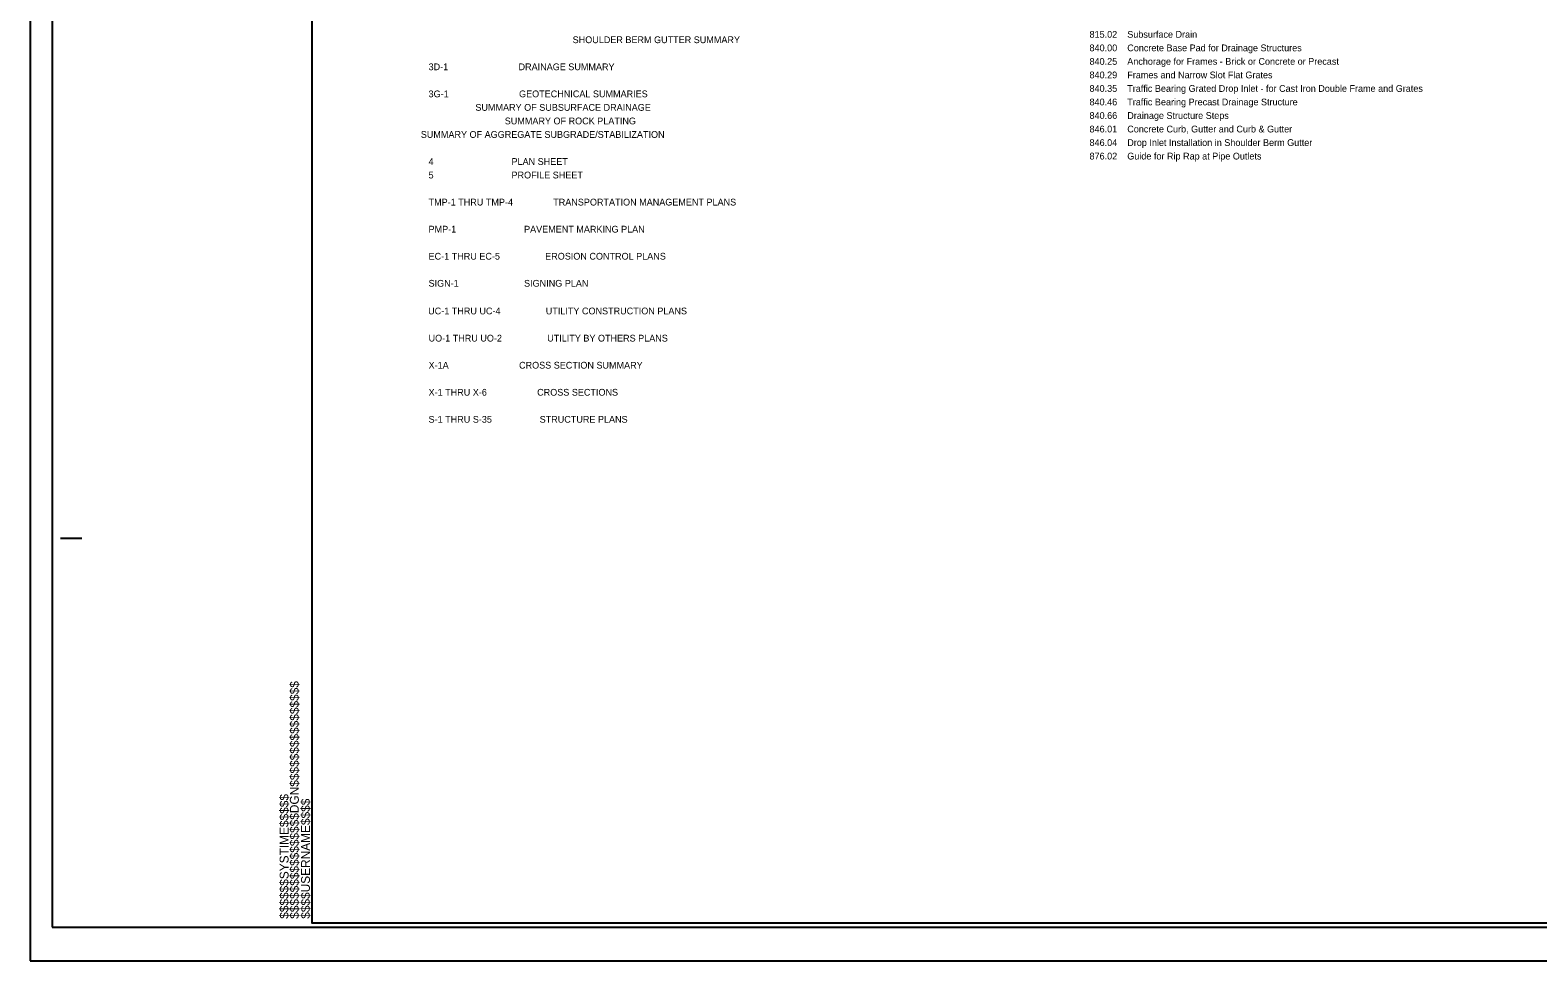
# Model space of a CAD drawing. Extents: x 9834 to 11517, y 9978 to 11072.
# Drawn here: x 9834 to 10725, y 9978 to 10528 of the extents above; entities that cross this region are included whole.
import ezdxf

# ---------------------------------------------------------------- set-up
doc = ezdxf.new("R2010")
doc.units = 0
for name, color, linetype in [('Default', 7, 'Continuous'), ('Sheet Cutting Line CELL', 7, 'Continuous'), ('Sheet Plan CELL', 7, 'Continuous'), ('Sheet Plot Border Inside CELL', 7, 'Continuous'), ('Sheet Plot Border Outside CELL', 7, 'Continuous')]:
    doc.layers.add(name, color=color, linetype=linetype)

msp = doc.modelspace()

# ---------------------------------------------------------------- linework, layer by layer
at = {"layer": 'Sheet Cutting Line CELL'}
for p, q in [((9833.5, 11072.5), (9833.5, 9977.5)), ((9833.5, 9977.5), (11517, 9977.5))]:
    msp.add_line(p, q, dxfattribs=at)
at = {"layer": 'Sheet Plan CELL'}
for p, q in [((9851.5, 10227.5), (9864, 10227.5)), ((10000, 10000), (10000, 10000))]:
    msp.add_line(p, q, dxfattribs=at)
msp.add_lwpolyline([(11500, 11050), (10000, 11050), (10000, 10000), (11500, 10000)], close=True, dxfattribs=at)
at = {"layer": 'Sheet Plot Border Inside CELL'}
msp.add_lwpolyline([(9846.5, 9997.5), (11512.5, 9997.5), (11512.5, 11052.5), (9846.5, 11052.5)], close=True, dxfattribs=at)
at = {"layer": 'Sheet Plot Border Outside CELL'}
msp.add_lwpolyline([(9833.5, 9977.5), (11517, 9977.5), (11517, 11072.5), (9833.5, 11072.5)], close=True, dxfattribs=at)

# ---------------------------------------------------------------- texts
at = {"layer": 'Default'}
for s, p in [('                 SHOULDER BERM GUTTER SUMMARY', (10129.01, 10520.13)), ('815.02    Subsurface Drain', (10459.92, 10523.33)), ('840.00    Concrete Base Pad for Drainage Structures', (10459.92, 10515.33)), ('840.25    Anchorage for Frames - Brick or Concrete or Precast', (10459.92, 10507.33)), ('3D-1                            DRAINAGE SUMMARY', (10069.09, 10504.13)), ('840.29    Frames and Narrow Slot Flat Grates', (10459.92, 10499.33)), ('840.35    Traffic Bearing Grated Drop Inlet - for Cast Iron Double Frame and Grates', (10459.92, 10491.33)), ('3G-1                            GEOTECHNICAL SUMMARIES', (10069.09, 10488.13)), ('                                        SUMMARY OF SUBSURFACE DRAINAGE', (10037.34, 10480.13)), ('840.46    Traffic Bearing Precast Drainage Structure', (10459.92, 10483.33)), ('                                 SUMMARY OF ROCK PLATING', (10065.1, 10472.13)), ('840.66    Drainage Structure Steps', (10459.92, 10475.33)), ('                                                     SUMMARY OF AGGREGATE SUBGRADE/STABILIZATION', (9985.73, 10464.13)), ('846.01    Concrete Curb, Gutter and Curb & Gutter', (10459.92, 10467.33)), ('846.04    Drop Inlet Installation in Shoulder Berm Gutter', (10459.92, 10459.33)), ('4                               PLAN SHEET', (10069.09, 10448.13)), ('876.02    Guide for Rip Rap at Pipe Outlets', (10459.92, 10451.33)), ('5                               PROFILE SHEET', (10069.09, 10440.13)), ('TMP-1 THRU TMP-4                TRANSPORTATION MANAGEMENT PLANS', (10069.09, 10424.13)), ('PMP-1                           PAVEMENT MARKING PLAN', (10069.09, 10408.13)), ('EC-1 THRU EC-5                  EROSION CONTROL PLANS', (10069.09, 10392.13)), ('SIGN-1                          SIGNING PLAN', (10069.09, 10376.13)), ('UC-1 THRU UC-4                  UTILITY CONSTRUCTION PLANS', (10068.85, 10359.77)), ('UO-1 THRU UO-2                  UTILITY BY OTHERS PLANS', (10069.09, 10343.69)), ('X-1A                            CROSS SECTION SUMMARY', (10069.09, 10327.69)), ('X-1 THRU X-6                    CROSS SECTIONS', (10069.09, 10311.69)), ('S-1 THRU S-35                   STRUCTURE PLANS', (10069.09, 10295.69))]:
    msp.add_text(s, height=4, dxfattribs=at).set_placement(p)
at = {"layer": 'Sheet Plan CELL'}
for s, p in [('$$$$$$$$$$$$$$$$DGN$$$$$$$$$$$$$$$$', (9992.35, 10002.36)), ('$$$$$$SYSTIME$$$$$', (9986.3, 10002.36)), ('$$$$USERNAME$$$$', (9998.93, 10002.38))]:
    msp.add_text(s, height=5.25, rotation=90, dxfattribs=at).set_placement(p)

doc.saveas('drawing.dxf')
